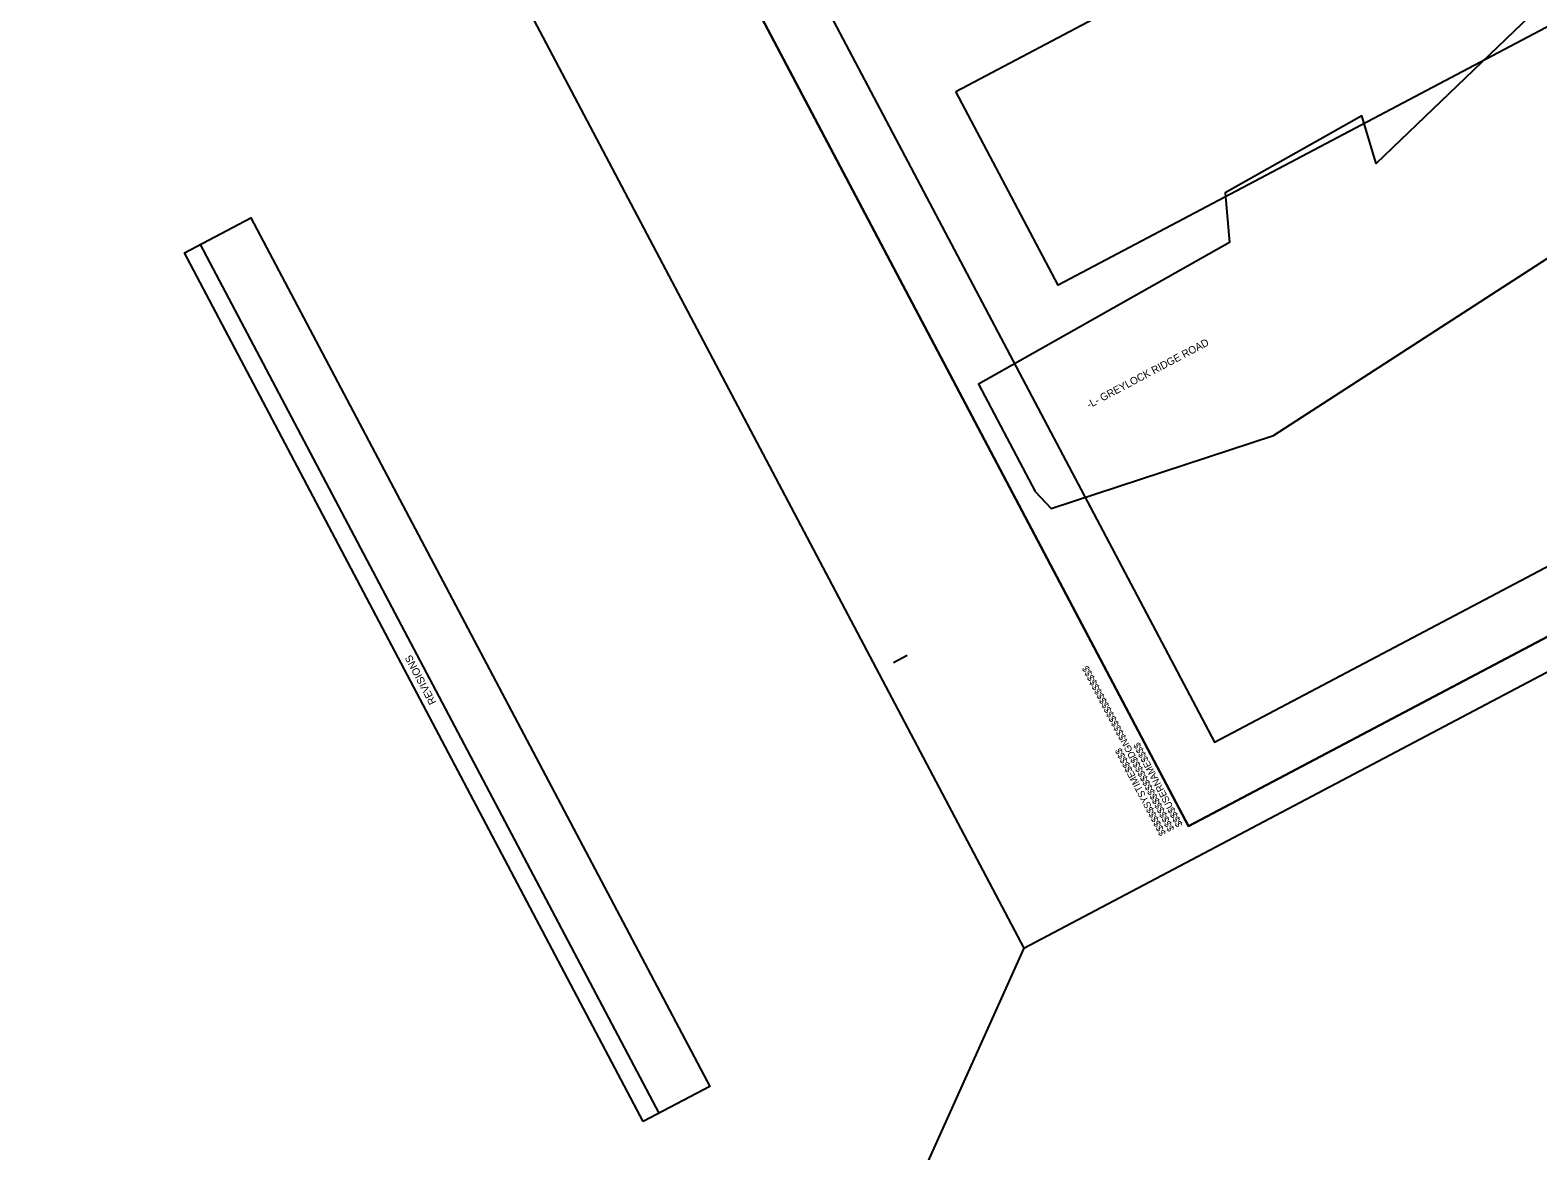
# Model space of a CAD drawing. Extents: x 1487052 to 1489663, y 496209 to 500965.
# Drawn here: x 1487052 to 1488265, y 497818 to 498720 of the extents above; entities that cross this region are included whole.
import ezdxf

# ---------------------------------------------------------------- set-up
doc = ezdxf.new("R2010")
doc.units = 0
for name, color, linetype in [('DEV TYPE 3 BARRICADE SECTION CELL', 7, 'Continuous'), ('DEV TYPE 3 BARRICADE SINGLE WITH R11-2 CELL', 7, 'Continuous'), ('Scratch_Level_0', 7, 'Continuous'), ('Scratch_Level_2', 7, 'Continuous'), ('Scratch_Level_3', 7, 'Continuous'), ('Sheet Block Revision CELL', 7, 'Continuous'), ('Sheet Plot Border Outside CELL', 7, 'Continuous'), ('Text', 7, 'Continuous')]:
    doc.layers.add(name, color=color, linetype=linetype)

msp = doc.modelspace()

# ---------------------------------------------------------------- linework, layer by layer
at = {"layer": 'DEV TYPE 3 BARRICADE SINGLE WITH R11-2 CELL'}
msp.add_lwpolyline([(1488799.3, 499640.6), (1487561.2, 498986.9), (1488004.8, 498146.9), (1488782, 498557.2), (1488726.8, 498661.8), (1489187.6, 498905.1)], close=True, dxfattribs=at)
at = {"layer": 'Scratch_Level_0'}
for p, q in [((1487746.4, 498211.1), (1487757.5, 498217)), ((1487984, 498079.3), (1487984, 498079.3))]:
    msp.add_line(p, q, dxfattribs=at)
msp.add_lwpolyline([(1488820.1, 499708.2), (1487493.7, 499007.8), (1487984, 498079.3), (1489310.4, 498779.7)], close=True, dxfattribs=at)
at = {"layer": 'Scratch_Level_2'}
msp.add_lwpolyline([(1487796.6, 498670.7), (1488308.9, 498941.3), (1488391.2, 498785.3), (1487878.9, 498514.8)], close=True, dxfattribs=at)
at = {"layer": 'Scratch_Level_3'}
msp.add_lwpolyline([(1487493.7, 499007.8), (1488662.1, 499625.8), (1488820.1, 499708.2), (1489310.4, 498779.7), (1487984, 498079.3)], close=True, dxfattribs=at)
msp.add_lwpolyline([(1487493.7, 499007.8), (1488662.1, 499625.8), (1488820.1, 499708.2), (1489310.4, 498779.7), (1487984, 498079.3)], close=True, dxfattribs=at)
for points in [[(1487860.6, 498348.6), (1487873.5, 498334.9), (1488052.4, 498393.7), (1488380.4, 498605.8), (1488680.8, 498962.7), (1488788.1, 498980.4), (1488817.5, 499053.9), (1488921.5, 499149.2), (1488934.2, 499155.9), (1488938.1, 499157.8), (1488970.3, 499133.5), (1489001.4, 499092.4), (1489035.9, 499035.8), (1489073.6, 499043.8), (1488988.2, 499184.2), (1488995.1, 499319.4), (1488997.6, 499386.6), (1488980.8, 499401.1), (1488871.5, 499364.9), (1488806.5, 499268.1), (1488743.2, 499201.1), (1488700.8, 499169.5), (1488617.1, 499075)], [(1488617.1, 499075), (1488135, 498612.7), (1488123.4, 498651), (1488013.4, 498588.9), (1488016.8, 498549), (1487814.9, 498435.1), (1487860.6, 498348.6)]]:
    msp.add_lwpolyline(points, dxfattribs=at)
at = {"layer": 'Sheet Block Revision CELL'}
msp.add_line((1487557.9, 497848.3), (1487188.7, 498547.4), dxfattribs=at)
msp.add_lwpolyline([(1487545, 497841.5), (1487175.9, 498540.6), (1487229.4, 498568.9), (1487598.6, 497869.7)], close=True, dxfattribs=at)
at = {"layer": 'Sheet Plot Border Outside CELL'}
msp.add_lwpolyline([(1487851.5, 497981.1), (1489344.2, 498769.3), (1488830.6, 499742), (1487337.9, 498953.8)], close=True, dxfattribs=at)
at = {"layer": 'Text'}
msp.add_line((1487851.5, 497981.1), (1487051.7, 496209.3), dxfattribs=at)

# ---------------------------------------------------------------- texts
at = {"layer": 'DEV TYPE 3 BARRICADE SECTION CELL'}
msp.add_text('-L- GREYLOCK RIDGE ROAD', height=6, rotation=27.895, dxfattribs=at).set_placement((1487904, 498415.4))
at = {"layer": 'Scratch_Level_0'}
for s, p in [('$$$$$$$$$$$$$$$$DGN$$$$$$$$$$$$$$$$', (1487972.7, 498076.8)), ('$$$$$$SYSTIME$$$$$', (1487966, 498073.3)), ('$$$$USERNAME$$$$', (1487979.4, 498080.4))]:
    msp.add_text(s, height=5.584, rotation=117.8351, dxfattribs=at).set_placement(p)
at = {"layer": 'Sheet Block Revision CELL'}
msp.add_text('REVISIONS', height=6, rotation=117.8351, dxfattribs=at).set_placement((1487378.7, 498179))

doc.saveas('drawing.dxf')
